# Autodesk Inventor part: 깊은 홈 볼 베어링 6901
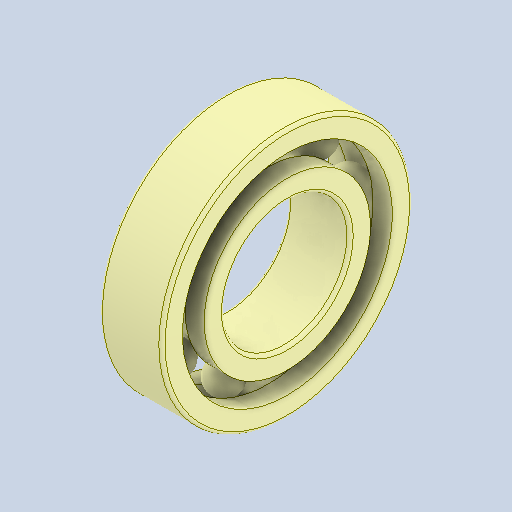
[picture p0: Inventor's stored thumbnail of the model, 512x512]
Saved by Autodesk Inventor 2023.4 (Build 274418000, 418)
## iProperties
Created: 2024-05
Part Number: 깊은 홈 볼 베어링 6901
Material: 강철, 연강
Description: 깊은 그루브 볼 베어링
Document SubType Name: Modeling
Designer: edu-40
Density: 7.85 g/cm^3
Appearance: 기본값
Author: jhkim
Sending System: Autodesk Inventor 2025
Preprocessor: ST-DEVELOPER v20
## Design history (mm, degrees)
feature "Solid1"
feature "Solid1:1"
feature "Solid1:2"
feature "Solid1:3"
feature "Solid1:4"
feature "Solid1:5"
feature "Solid1:6"
feature "Solid1:7"
feature "Solid1:8"
feature "Solid1:9"
feature "Solid1:10"
node "솔리드1"
node "솔리드2"
node "솔리드3"
node "솔리드4"
node "솔리드5"
node "솔리드6"
node "솔리드7"
node "솔리드8"
node "솔리드9"
node "솔리드10"
node "솔리드11"
